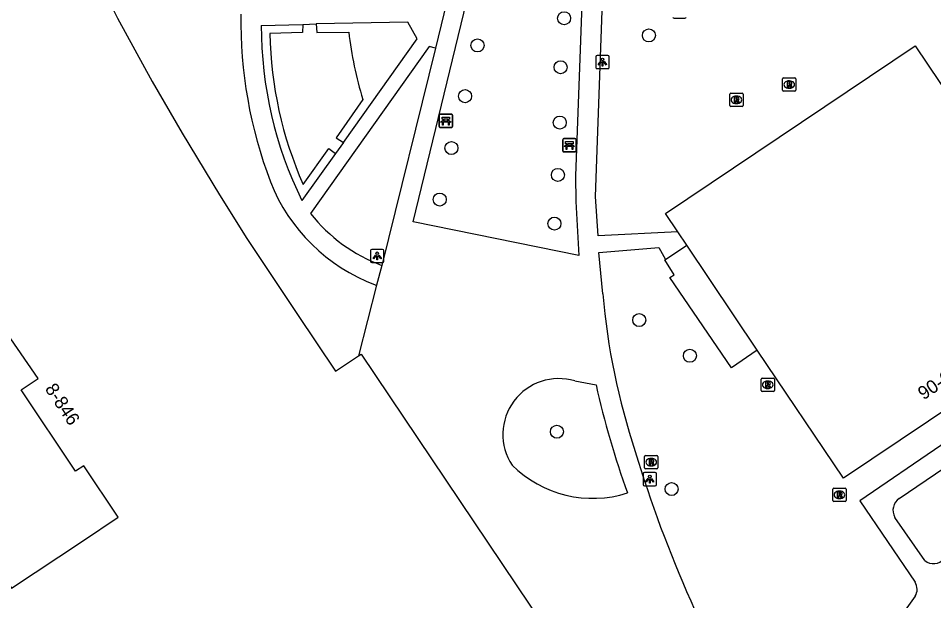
# Model space of a CAD drawing. Extents: x 159675 to 160530, y 382179 to 382901.
# Drawn here: x 159903.7 to 159972.5, y 382455.4 to 382499.1 of the extents above; entities that cross this region are included whole.
import ezdxf

# ---------------------------------------------------------------- set-up
doc = ezdxf.new("R2010")
doc.units = 0
for name, color, linetype in [('IMGEO_Bank', 7, 'Continuous'), ('IMGEO_Boom', 7, 'Continuous'), ('IMGEO_Lichtpunt', 7, 'Continuous'), ('IMGEO_Pand', 7, 'Continuous'), ('IMGEO_Pand_nummerreeks', 7, 'Continuous'), ('IMGEO_Rioolput', 7, 'Continuous'), ('IMGEO_Voetpad_gesloten', 7, 'Continuous'), ('IMGEO_Voetpad_halfverhard', 7, 'Continuous'), ('IMGEO_Voetpad_open', 7, 'Continuous')]:
    doc.layers.add(name, color=color, linetype=linetype)

msp = doc.modelspace()

# ---------------------------------------------------------------- linework, layer by layer
at = {"layer": 'IMGEO_Bank'}
for p, q in [((159935.341, 382491.009), (159935.341, 382491.85)), ((159935.341, 382491.85), (159935.341, 382491.009)), ((159935.416, 382491.934), (159936.257, 382491.934)), ((159936.257, 382491.934), (159935.416, 382491.934)), ((159936.341, 382491.859), (159936.341, 382491.018)), ((159936.341, 382491.018), (159936.341, 382491.859)), ((159936.038, 382491.332), (159935.645, 382491.332)), ((159935.65, 382491.44), (159935.65, 382491.546)), ((159935.694, 382491.546), (159935.694, 382491.44)), ((159935.982, 382491.552), (159935.7, 382491.552)), ((159935.7, 382491.434), (159935.982, 382491.434)), ((159935.988, 382491.44), (159935.988, 382491.546)), ((159936.032, 382491.546), (159936.032, 382491.44)), ((159936.266, 382490.934), (159935.425, 382490.934)), ((159935.425, 382490.934), (159936.266, 382490.934)), ((159944.623, 382489.169), (159944.623, 382490.01)), ((159944.623, 382490.01), (159944.623, 382489.169)), ((159944.698, 382490.094), (159945.539, 382490.094)), ((159945.539, 382490.094), (159944.698, 382490.094)), ((159945.623, 382490.019), (159945.623, 382489.178)), ((159945.623, 382489.178), (159945.623, 382490.019)), ((159945.548, 382489.094), (159944.707, 382489.094)), ((159944.707, 382489.094), (159945.548, 382489.094)), ((159945.32, 382489.492), (159944.927, 382489.492)), ((159944.932, 382489.6), (159944.932, 382489.706)), ((159944.976, 382489.706), (159944.976, 382489.6)), ((159945.264, 382489.712), (159944.982, 382489.712)), ((159944.982, 382489.594), (159945.264, 382489.594)), ((159945.27, 382489.6), (159945.27, 382489.706)), ((159945.314, 382489.706), (159945.314, 382489.6))]:
    msp.add_line(p, q, dxfattribs=at)
for points in [[(159935.588, 382491.332), (159935.446, 382491.332), (159935.558, 382491.434), (159935.644, 382491.434)], [(159935.644, 382491.552), (159935.558, 382491.552), (159935.558, 382491.713), (159936.121, 382491.713), (159936.121, 382491.552), (159936.038, 382491.552)], [(159935.638, 382491.325), (159935.638, 382491.118), (159935.595, 382491.118), (159935.595, 382491.325)], [(159936.038, 382491.434), (159936.121, 382491.434), (159936.233, 382491.332), (159936.094, 382491.332)], [(159936.088, 382491.325), (159936.088, 382491.118), (159936.044, 382491.118), (159936.044, 382491.325)], [(159944.926, 382489.712), (159944.84, 382489.712), (159944.84, 382489.873), (159945.403, 382489.873), (159945.403, 382489.712), (159945.32, 382489.712)], [(159944.87, 382489.492), (159944.728, 382489.492), (159944.84, 382489.594), (159944.926, 382489.594)], [(159944.92, 382489.485), (159944.92, 382489.278), (159944.877, 382489.278), (159944.877, 382489.485)], [(159945.32, 382489.594), (159945.403, 382489.594), (159945.515, 382489.492), (159945.376, 382489.492)], [(159945.37, 382489.485), (159945.37, 382489.278), (159945.326, 382489.278), (159945.326, 382489.485)]]:
    msp.add_lwpolyline(points, dxfattribs=at)
for centre, radius, start, end in [((159935.419, 382491.856), 0.0779, 92.4484, 184.28452), ((159935.419, 382491.856), 0.0779, 92.4484, 184.28452), ((159936.263, 382491.856), 0.0779, 2.4484, 94.28452), ((159936.263, 382491.856), 0.0779, 2.4484, 94.28452), ((159935.588, 382491.325), 0.00671, 2.89567, 87.10433), ((159935.645, 382491.325), 0.00671, 92.89567, 177.10433), ((159935.643, 382491.545), 0.00671, 2.89567, 87.10433), ((159935.643, 382491.441), 0.00671, 272.89567, 357.10433), ((159935.7, 382491.545), 0.00671, 92.89567, 177.10433), ((159935.7, 382491.441), 0.00671, 182.89567, 267.10433), ((159935.982, 382491.545), 0.00671, 2.89567, 87.10433), ((159935.982, 382491.441), 0.00671, 272.89567, 357.10433), ((159936.039, 382491.545), 0.00671, 92.89567, 177.10433), ((159936.039, 382491.441), 0.00671, 182.89567, 267.10433), ((159936.037, 382491.325), 0.00671, 2.89567, 87.10433), ((159936.094, 382491.325), 0.00671, 92.89567, 177.10433), ((159935.419, 382491.012), 0.0779, 182.4484, 274.28452), ((159935.419, 382491.012), 0.0779, 182.4484, 274.28452), ((159936.263, 382491.012), 0.0779, 272.4484, 4.28452), ((159936.263, 382491.012), 0.0779, 272.4484, 4.28452), ((159944.701, 382490.016), 0.0779, 92.4484, 184.28452), ((159944.701, 382490.016), 0.0779, 92.4484, 184.28452), ((159945.545, 382490.016), 0.0779, 2.4484, 94.28452), ((159945.545, 382490.016), 0.0779, 2.4484, 94.28452), ((159944.701, 382489.172), 0.0779, 182.4484, 274.28452), ((159944.701, 382489.172), 0.0779, 182.4484, 274.28452), ((159944.87, 382489.485), 0.00671, 2.89567, 87.10433), ((159944.927, 382489.485), 0.00671, 92.89567, 177.10433), ((159944.925, 382489.705), 0.00671, 2.89567, 87.10433), ((159944.925, 382489.601), 0.00671, 272.89567, 357.10433), ((159944.982, 382489.705), 0.00671, 92.89567, 177.10433), ((159944.982, 382489.601), 0.00671, 182.89567, 267.10433), ((159945.264, 382489.705), 0.00671, 2.89567, 87.10433), ((159945.264, 382489.601), 0.00671, 272.89567, 357.10433), ((159945.321, 382489.705), 0.00671, 92.89567, 177.10433), ((159945.321, 382489.601), 0.00671, 182.89567, 267.10433), ((159945.319, 382489.485), 0.00671, 2.89567, 87.10433), ((159945.376, 382489.485), 0.00671, 92.89567, 177.10433), ((159945.545, 382489.172), 0.0779, 272.4484, 4.28452), ((159945.545, 382489.172), 0.0779, 272.4484, 4.28452)]:
    msp.add_arc(centre, radius, start, end, dxfattribs=at)
at = {"layer": 'IMGEO_Boom'}
for centre in [(159944.726, 382499.143), (159951.094, 382497.85), (159938.219, 382497.1), (159944.464, 382495.46), (159937.284, 382493.286), (159944.4, 382491.304), (159936.263, 382489.39), (159944.261, 382487.368), (159935.38, 382485.519), (159943.999, 382483.706), (159950.366, 382476.465), (159954.172, 382473.778), (159944.184, 382468.073), (159952.803, 382463.765)]:
    msp.add_circle(centre, 0.489, dxfattribs=at)
at = {"layer": 'IMGEO_Lichtpunt'}
for p, q in [((159952.988, 382499.138), (159953.796, 382499.138)), ((159952.988, 382499.138), (159953.796, 382499.138)), ((159947.105, 382496.254), (159947.105, 382495.447)), ((159947.105, 382496.254), (159947.105, 382495.447)), ((159948.007, 382496.349), (159947.199, 382496.349)), ((159948.007, 382496.349), (159947.199, 382496.349)), ((159948.101, 382495.447), (159948.101, 382496.254)), ((159948.101, 382495.447), (159948.101, 382496.254)), ((159947.199, 382495.353), (159948.007, 382495.353)), ((159947.199, 382495.353), (159948.007, 382495.353)), ((159930.187, 382481.681), (159930.187, 382480.874)), ((159930.187, 382481.681), (159930.187, 382480.874)), ((159931.089, 382481.776), (159930.281, 382481.776)), ((159931.089, 382481.776), (159930.281, 382481.776)), ((159931.183, 382480.874), (159931.183, 382481.681)), ((159931.183, 382480.874), (159931.183, 382481.681)), ((159930.281, 382480.78), (159931.089, 382480.78)), ((159930.281, 382480.78), (159931.089, 382480.78)), ((159951.563, 382464.999), (159950.755, 382464.999)), ((159951.563, 382464.999), (159950.755, 382464.999)), ((159950.661, 382464.904), (159950.661, 382464.097)), ((159950.661, 382464.904), (159950.661, 382464.097)), ((159951.657, 382464.097), (159951.657, 382464.904)), ((159951.657, 382464.097), (159951.657, 382464.904)), ((159950.755, 382464.003), (159951.563, 382464.003)), ((159950.755, 382464.003), (159951.563, 382464.003))]:
    msp.add_line(p, q, dxfattribs=at)
for points in [[(159947.479, 382495.918), (159947.518, 382495.89), (159947.33, 382495.628), (159947.292, 382495.655), (159947.479, 382495.918)], [(159947.691, 382495.89), (159947.729, 382495.917), (159947.916, 382495.655), (159947.877, 382495.627), (159947.691, 382495.89)], [(159947.581, 382495.87), (159947.628, 382495.87), (159947.628, 382495.548), (159947.581, 382495.548), (159947.581, 382495.87)], [(159930.561, 382481.345), (159930.6, 382481.317), (159930.412, 382481.055), (159930.374, 382481.082), (159930.561, 382481.345)], [(159930.663, 382481.297), (159930.71, 382481.297), (159930.71, 382480.975), (159930.663, 382480.975), (159930.663, 382481.297)], [(159930.773, 382481.317), (159930.811, 382481.344), (159930.998, 382481.082), (159930.959, 382481.054), (159930.773, 382481.317)], [(159951.035, 382464.568), (159951.074, 382464.54), (159950.886, 382464.278), (159950.848, 382464.305), (159951.035, 382464.568)], [(159951.137, 382464.52), (159951.184, 382464.52), (159951.184, 382464.198), (159951.137, 382464.198), (159951.137, 382464.52)], [(159951.247, 382464.54), (159951.285, 382464.567), (159951.472, 382464.305), (159951.433, 382464.277), (159951.247, 382464.54)]]:
    msp.add_lwpolyline(points, dxfattribs=at)
for centre in [(159947.604, 382496.052), (159930.686, 382481.479), (159951.16, 382464.702)]:
    msp.add_circle(centre, 0.0994, dxfattribs=at)
for centre, start, end in [((159952.988, 382499.232), 180, 270), ((159952.988, 382499.232), 180, 270), ((159953.796, 382499.232), 270, 0), ((159953.796, 382499.232), 270, 360), ((159947.199, 382496.254), 90, 180), ((159947.199, 382496.254), 90, 180), ((159948.007, 382496.254), 0, 90), ((159948.007, 382496.254), 0, 90), ((159947.199, 382495.447), 180, 270), ((159947.199, 382495.447), 180, 270), ((159948.007, 382495.447), 270, 0), ((159948.007, 382495.447), 270, 360), ((159930.281, 382481.681), 90, 180), ((159930.281, 382481.681), 90, 180), ((159931.089, 382481.681), 0, 90), ((159931.089, 382481.681), 0, 90), ((159930.281, 382480.874), 180, 270), ((159930.281, 382480.874), 180, 270), ((159931.089, 382480.874), 270, 0), ((159931.089, 382480.874), 270, 360), ((159950.755, 382464.904), 90, 180), ((159950.755, 382464.904), 90, 180), ((159951.563, 382464.904), 0, 90), ((159951.563, 382464.904), 0, 90), ((159950.755, 382464.097), 180, 270), ((159950.755, 382464.097), 180, 270), ((159951.563, 382464.097), 270, 0), ((159951.563, 382464.097), 270, 360)]:
    msp.add_arc(centre, 0.0946, start, end, dxfattribs=at)
at = {"layer": 'IMGEO_Pand'}
for points in [[(159921.255, 382524.225), (159905.429, 382510.573), (159906.654, 382508.016), (159908.792, 382503.757), (159910.743, 382500), (159911.188, 382499.142), (159913.789, 382494.394), (159916.043, 382490.496), (159918.836, 382485.861), (159920.894, 382482.597), (159924.587, 382477.025), (159924.687, 382476.874), (159927.556, 382472.629), (159929.284, 382473.78)], [(159953.275, 382483.094), (159952.337, 382484.474), (159971.108, 382497.075), (159977.69, 382487.272)], [(159978.552, 382485.987), (159984.462, 382477.186), (159972.103, 382468.865), (159965.701, 382464.59), (159959.223, 382474.207)], [(159953.953, 382482.094), (159953.275, 382483.094)], [(159959.223, 382474.207), (159953.953, 382482.094)], [(159900.383, 382456.268), (159902.344, 382457.591), (159903.211, 382456.306), (159908.541, 382459.857), (159911.217, 382461.64), (159908.638, 382465.51), (159908.014, 382465.094), (159903.939, 382471.211), (159905.207, 382472.058), (159902.877, 382475.458)], [(159929.284, 382473.78), (159929.473, 382473.906), (159946.417, 382448.7)]]:
    msp.add_lwpolyline(points, dxfattribs=at)
at = {"layer": 'IMGEO_Rioolput'}
for p, q in [((159961.135, 382493.73), (159961.135, 382494.582)), ((159961.21, 382494.656), (159962.062, 382494.656)), ((159962.136, 382494.582), (159962.136, 382493.73)), ((159961.646, 382493.876), (159961.621, 382493.876)), ((159961.623, 382494.436), (159961.648, 382494.436)), ((159957.168, 382492.585), (159957.168, 382493.437)), ((159957.243, 382493.511), (159958.095, 382493.511)), ((159957.656, 382493.291), (159957.681, 382493.291)), ((159958.169, 382493.437), (159958.169, 382492.585)), ((159962.062, 382493.656), (159961.21, 382493.656)), ((159958.095, 382492.511), (159957.243, 382492.511)), ((159957.679, 382492.731), (159957.654, 382492.731)), ((159959.523, 382471.174), (159959.523, 382472.026)), ((159959.598, 382472.1), (159960.45, 382472.1)), ((159960.011, 382471.88), (159960.036, 382471.88)), ((159960.524, 382472.026), (159960.524, 382471.174)), ((159960.034, 382471.32), (159960.009, 382471.32)), ((159960.45, 382471.1), (159959.598, 382471.1)), ((159950.766, 382465.358), (159950.766, 382466.21)), ((159950.841, 382466.284), (159951.693, 382466.284)), ((159951.254, 382466.064), (159951.279, 382466.064)), ((159951.767, 382466.21), (159951.767, 382465.358)), ((159951.693, 382465.284), (159950.841, 382465.284)), ((159951.277, 382465.504), (159951.252, 382465.504)), ((159964.911, 382462.9), (159964.911, 382463.752)), ((159964.986, 382463.826), (159965.838, 382463.826)), ((159965.399, 382463.606), (159965.424, 382463.606)), ((159965.912, 382463.752), (159965.912, 382462.9)), ((159965.422, 382463.046), (159965.397, 382463.046)), ((159965.838, 382462.826), (159964.986, 382462.826))]:
    msp.add_line(p, q, dxfattribs=at)
for points in [[(159961.135, 382493.73), (159961.135, 382494.582)], [(159961.21, 382494.656), (159962.062, 382494.656)], [(159962.136, 382494.582), (159962.136, 382493.73)], [(159961.724, 382494.354), (159961.472, 382494.356), (159961.472, 382493.956)], [(159961.472, 382493.956), (159961.596, 382493.956), (159961.596, 382494.118), (159961.607, 382494.118)], [(159961.65, 382494.275), (159961.596, 382494.275), (159961.596, 382494.194)], [(159961.596, 382494.194), (159961.648, 382494.194)], [(159961.654, 382494.089), (159961.725, 382493.956), (159961.865, 382493.956), (159961.8, 382494.082)], [(159957.168, 382492.585), (159957.168, 382493.437)], [(159957.243, 382493.511), (159958.095, 382493.511)], [(159957.757, 382493.209), (159957.505, 382493.211), (159957.505, 382492.811)], [(159958.169, 382493.437), (159958.169, 382492.585)], [(159962.062, 382493.656), (159961.21, 382493.656)], [(159958.095, 382492.511), (159957.243, 382492.511)], [(159957.505, 382492.811), (159957.629, 382492.811), (159957.629, 382492.973), (159957.64, 382492.973)], [(159957.683, 382493.13), (159957.629, 382493.13), (159957.629, 382493.049)], [(159957.629, 382493.049), (159957.681, 382493.049)], [(159957.687, 382492.944), (159957.758, 382492.811), (159957.898, 382492.811), (159957.833, 382492.937)], [(159959.523, 382471.174), (159959.523, 382472.026)], [(159959.598, 382472.1), (159960.45, 382472.1)], [(159960.524, 382472.026), (159960.524, 382471.174)], [(159960.112, 382471.798), (159959.86, 382471.8), (159959.86, 382471.4)], [(159959.86, 382471.4), (159959.984, 382471.4), (159959.984, 382471.562), (159959.995, 382471.562)], [(159960.038, 382471.719), (159959.984, 382471.719), (159959.984, 382471.638)], [(159959.984, 382471.638), (159960.036, 382471.638)], [(159960.042, 382471.533), (159960.113, 382471.4), (159960.253, 382471.4), (159960.188, 382471.526)], [(159960.45, 382471.1), (159959.598, 382471.1)], [(159950.766, 382465.358), (159950.766, 382466.21)], [(159950.841, 382466.284), (159951.693, 382466.284)], [(159951.355, 382465.982), (159951.103, 382465.984), (159951.103, 382465.584)], [(159951.103, 382465.584), (159951.227, 382465.584), (159951.227, 382465.746), (159951.238, 382465.746)], [(159951.281, 382465.903), (159951.227, 382465.903), (159951.227, 382465.822)], [(159951.227, 382465.822), (159951.279, 382465.822)], [(159951.285, 382465.717), (159951.356, 382465.584), (159951.496, 382465.584), (159951.431, 382465.71)], [(159951.767, 382466.21), (159951.767, 382465.358)], [(159951.693, 382465.284), (159950.841, 382465.284)], [(159964.911, 382462.9), (159964.911, 382463.752)], [(159964.986, 382463.826), (159965.838, 382463.826)], [(159965.912, 382463.752), (159965.912, 382462.9)], [(159965.5, 382463.524), (159965.248, 382463.526), (159965.248, 382463.126)], [(159965.248, 382463.126), (159965.372, 382463.126), (159965.372, 382463.288), (159965.383, 382463.288)], [(159965.426, 382463.445), (159965.372, 382463.445), (159965.372, 382463.364)], [(159965.372, 382463.364), (159965.424, 382463.364)], [(159965.43, 382463.259), (159965.501, 382463.126), (159965.641, 382463.126), (159965.576, 382463.252)], [(159965.838, 382462.826), (159964.986, 382462.826)]]:
    msp.add_lwpolyline(points, dxfattribs=at)
for centre, radius, start, end in [((159961.212, 382494.58), 0.0765, 91.55205, 178.44795), ((159961.212, 382494.58), 0.0765, 91.55205, 178.44795), ((159962.06, 382494.58), 0.0765, 1.55205, 88.44795), ((159962.06, 382494.58), 0.0765, 1.55205, 88.44795), ((159961.606, 382494.065), 0.0533, 26.02933, 88.69889), ((159961.632, 382494.383), 0.19, 274.7715, 282.96867), ((159961.656, 382494.179), 0.0964, 77.00612, 93.18647), ((159961.67, 382494.236), 0.0378, 276.66336, 79.67722), ((159961.723, 382494.244), 0.109, 350.36119, 89.41601), ((159961.721, 382494.244), 0.112, 277.58423, 350.98172), ((159961.705, 382494.029), 0.108, 29.51342, 73.79051), ((159957.245, 382493.435), 0.0765, 91.55205, 178.44795), ((159957.245, 382493.435), 0.0765, 91.55205, 178.44795), ((159957.756, 382493.099), 0.109, 350.36119, 89.41601), ((159958.093, 382493.435), 0.0765, 1.55205, 88.44795), ((159958.093, 382493.435), 0.0765, 1.55205, 88.44795), ((159961.212, 382493.732), 0.0765, 181.55205, 268.44795), ((159961.212, 382493.732), 0.0765, 181.55205, 268.44795), ((159962.06, 382493.732), 0.0765, 271.55205, 358.44795), ((159962.06, 382493.732), 0.0765, 271.55205, 358.44795), ((159957.245, 382492.587), 0.0765, 181.55205, 268.44795), ((159957.245, 382492.587), 0.0765, 181.55205, 268.44795), ((159957.639, 382492.92), 0.0533, 26.02933, 88.69889), ((159957.665, 382493.238), 0.19, 274.7715, 282.96867), ((159957.689, 382493.034), 0.0964, 77.00612, 93.18647), ((159957.703, 382493.091), 0.0378, 276.66336, 79.67722), ((159957.754, 382493.099), 0.112, 277.58423, 350.98172), ((159957.738, 382492.884), 0.108, 29.51342, 73.79051), ((159958.093, 382492.587), 0.0765, 271.55205, 358.44795), ((159958.093, 382492.587), 0.0765, 271.55205, 358.44795), ((159959.6, 382472.024), 0.0765, 91.55205, 178.44795), ((159959.6, 382472.024), 0.0765, 91.55205, 178.44795), ((159960.448, 382472.024), 0.0765, 1.55205, 88.44795), ((159960.448, 382472.024), 0.0765, 1.55205, 88.44795), ((159959.6, 382471.176), 0.0765, 181.55205, 268.44795), ((159959.6, 382471.176), 0.0765, 181.55205, 268.44795), ((159959.994, 382471.509), 0.0533, 26.02933, 88.69889), ((159960.02, 382471.827), 0.19, 274.7715, 282.96867), ((159960.044, 382471.623), 0.0964, 77.00612, 93.18647), ((159960.058, 382471.68), 0.0378, 276.66336, 79.67722), ((159960.111, 382471.688), 0.109, 350.36119, 89.41601), ((159960.109, 382471.688), 0.112, 277.58423, 350.98172), ((159960.093, 382471.473), 0.108, 29.51342, 73.79051), ((159960.448, 382471.176), 0.0765, 271.55205, 358.44795), ((159960.448, 382471.176), 0.0765, 271.55205, 358.44795), ((159950.843, 382466.208), 0.0765, 91.55205, 178.44795), ((159950.843, 382466.208), 0.0765, 91.55205, 178.44795), ((159951.237, 382465.693), 0.0533, 26.02933, 88.69889), ((159951.263, 382466.011), 0.19, 274.7715, 282.96867), ((159951.287, 382465.807), 0.0964, 77.00612, 93.18647), ((159951.301, 382465.864), 0.0378, 276.66336, 79.67722), ((159951.354, 382465.872), 0.109, 350.36119, 89.41601), ((159951.352, 382465.872), 0.112, 277.58423, 350.98172), ((159951.336, 382465.657), 0.108, 29.51342, 73.79051), ((159951.691, 382466.208), 0.0765, 1.55205, 88.44795), ((159951.691, 382466.208), 0.0765, 1.55205, 88.44795), ((159950.843, 382465.36), 0.0765, 181.55205, 268.44795), ((159950.843, 382465.36), 0.0765, 181.55205, 268.44795), ((159951.691, 382465.36), 0.0765, 271.55205, 358.44795), ((159951.691, 382465.36), 0.0765, 271.55205, 358.44795), ((159964.988, 382463.75), 0.0765, 91.55205, 178.44795), ((159964.988, 382463.75), 0.0765, 91.55205, 178.44795), ((159965.836, 382463.75), 0.0765, 1.55205, 88.44795), ((159965.836, 382463.75), 0.0765, 1.55205, 88.44795), ((159964.988, 382462.902), 0.0765, 181.55205, 268.44795), ((159964.988, 382462.902), 0.0765, 181.55205, 268.44795), ((159965.382, 382463.235), 0.0533, 26.02933, 88.69889), ((159965.408, 382463.553), 0.19, 274.7715, 282.96867), ((159965.432, 382463.349), 0.0964, 77.00612, 93.18647), ((159965.446, 382463.406), 0.0378, 276.66336, 79.67722), ((159965.499, 382463.414), 0.109, 350.36119, 89.41601), ((159965.497, 382463.414), 0.112, 277.58423, 350.98172), ((159965.481, 382463.199), 0.108, 29.51342, 73.79051), ((159965.836, 382462.902), 0.0765, 271.55205, 358.44795), ((159965.836, 382462.902), 0.0765, 271.55205, 358.44795)]:
    msp.add_arc(centre, radius, start, end, dxfattribs=at)
for centre, major_axis, ratio, start_param, end_param in [((159961.622, 382494.156), (-0.387, 0.002), 0.722429, 4.712389, 7.853982), ((159961.647, 382494.156), (-0.39, 0.002), 0.717154, 1.570796, 4.712389), ((159957.655, 382493.011), (-0.387, 0.002), 0.722429, 4.712389, 7.853982), ((159957.68, 382493.011), (-0.39, 0.002), 0.717154, 1.570796, 4.712389), ((159960.01, 382471.6), (-0.387, 0.002), 0.722429, 4.712389, 7.853982), ((159960.035, 382471.6), (-0.39, 0.002), 0.717154, 1.570796, 4.712389), ((159951.253, 382465.784), (-0.387, 0.002), 0.722429, 4.712389, 7.853982), ((159951.278, 382465.784), (-0.39, 0.002), 0.717154, 1.570796, 4.712389), ((159965.398, 382463.326), (-0.387, 0.002), 0.722429, 4.712389, 7.853982), ((159965.423, 382463.326), (-0.39, 0.002), 0.717154, 1.570796, 4.712389)]:
    msp.add_ellipse(centre, major_axis=major_axis, ratio=ratio, start_param=start_param, end_param=end_param, dxfattribs=at)
at = {"layer": 'IMGEO_Voetpad_gesloten'}
for points in [[(159953.275, 382483.094), (159947.291, 382482.795), (159947.091, 382485.74), (159948.327, 382520.678)], [(159946.812, 382520.597), (159945.579, 382487.312), (159945.602, 382485.361), (159945.842, 382481.317), (159933.391, 382483.848), (159942.071, 382519.651)], [(159936.306, 382502.078), (159935.066, 382496.883)], [(159935.066, 382496.883), (159931.026, 382480.571)], [(159947.627, 382478.436), (159947.34, 382481.538), (159951.853, 382481.903), (159952.353, 382481.014)], [(159952.353, 382481.014), (159953.953, 382482.094)], [(159931.026, 382480.571), (159930.626, 382479.087)], [(159930.626, 382479.087), (159929.284, 382473.78)], [(159945.534, 382471.883), (159947.126, 382471.589)], [(159984.461, 382461.389), (159982.172, 382463.099), (159977.404, 382470.015), (159975.834, 382468.946), (159973.024, 382467.034), (159966.95, 382462.888), (159971.088, 382456.766)], [(159969.893, 382463.06), (159976.672, 382467.661)], [(159971.822, 382458.383), (159969.568, 382461.635)], [(159971.096, 382455.701), (159969.303, 382453.181), (159962.082, 382443.294)]]:
    msp.add_lwpolyline(points, dxfattribs=at)
for centre, radius, start, end in [((159999.331, 382482.921), 51.898, 184.95794, 198.35432), ((159944.322, 382467.864), 4.197, 73.2191, 213.32862), ((160010.525, 382485.679), 64.946, 192.53022, 200.00048), ((160041.512, 382494.145), 95.504, 196.77657, 203.95294), ((159946.893, 382471.723), 8.658, 225.40624, 287.49547), ((159970.522, 382462.167), 1.092, 125.14843, 209.15616), ((159972.466, 382459.191), 1.034, 231.43259, 321.02192), ((159970.235, 382456.227), 1.009, 328.56188, 32.29888), ((160032.462, 382488.485), 84.949, 202.94226, 210.62886)]:
    msp.add_arc(centre, radius, start, end, dxfattribs=at)
at = {"layer": 'IMGEO_Voetpad_halfverhard'}
for points in [[(159921.975, 382498.59), (159925.099, 382498.662)], [(159928.149, 382489.793), (159933.692, 382497.595), (159932.981, 382498.852), (159926.101, 382498.729)], [(159935.066, 382496.883), (159934.599, 382497.017), (159925.684, 382484.461)], [(159927.563, 382488.986), (159925.029, 382485.444)], [(159930.532, 382479.119), (159930.626, 382479.087)]]:
    msp.add_lwpolyline(points, dxfattribs=at)
for centre, radius, start, end in [((159954.557, 382498.975), 34.12, 179.20357, 200.80253), ((159951.794, 382498.59), 29.819, 179.99921, 206.15804), ((159935.308, 382491.849), 13.596, 201.54044, 249.43594), ((159935.273, 382492.016), 12.207, 218.2342, 249.64221)]:
    msp.add_arc(centre, radius, start, end, dxfattribs=at)
at = {"layer": 'IMGEO_Voetpad_open'}
for points in [[(159925.099, 382498.662), (159925.079, 382498.07), (159922.621, 382497.991)], [(159925.099, 382498.662), (159926.101, 382498.729)], [(159926.101, 382498.729), (159926.142, 382498.082), (159928.545, 382498.101)], [(159929.61, 382493.041), (159927.603, 382490.163), (159928.149, 382489.793)], [(159928.149, 382489.793), (159927.563, 382488.986)], [(159925.122, 382486.658), (159927.042, 382489.357), (159927.563, 382488.986)], [(159959.223, 382474.207), (159957.306, 382472.872), (159952.667, 382479.665), (159953.001, 382479.864), (159952.294, 382480.975), (159952.353, 382481.014)]]:
    msp.add_lwpolyline(points, dxfattribs=at)
for centre, radius, start, end in [((159952.076, 382498.549), 29.46, 181.08462, 203.80486), ((159957.004, 382501.449), 28.655, 186.70916, 197.06245)]:
    msp.add_arc(centre, radius, start, end, dxfattribs=at)

# ---------------------------------------------------------------- texts
at = {"layer": 'IMGEO_Pand_nummerreeks'}
for s, rotation, p in [('90-600', 33.95204, (159971.728, 382470.421)), ('8-846', 303.67366, (159905.687, 382471.292))]:
    msp.add_text(s, height=1, rotation=rotation, dxfattribs=at).set_placement(p)

doc.saveas('drawing.dxf')
